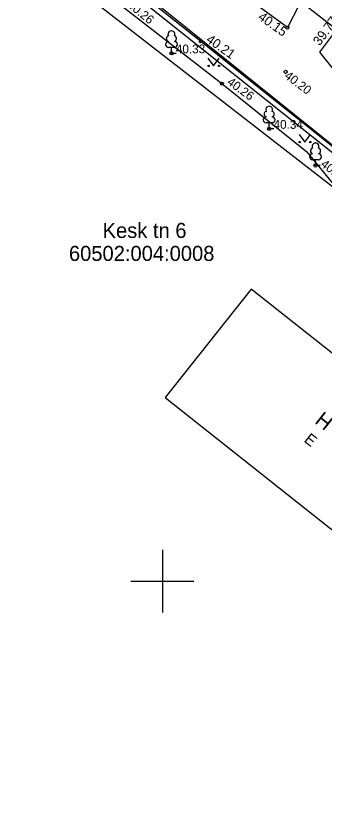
# Model space of a CAD drawing. Extents: x 641898 to 642452, y 6471715 to 6472255.
# Drawn here: x 642288.3 to 642312.9, y 6471781.7 to 6471845.1 of the extents above; entities that cross this region are included whole.
import ezdxf

# ---------------------------------------------------------------- set-up
doc = ezdxf.new("R2010")
doc.units = 0
for name, color, linetype in [('HALJASTUS', 7, 'Continuous'), ('HOONE', 7, 'Continuous'), ('KORGUS-EH2000', 7, 'Continuous'), ('KTRASS', 7, 'Continuous'), ('PIIR', 7, 'Continuous'), ('PUU', 7, 'Continuous'), ('TEE', 7, 'Continuous'), ('VORK', 7, 'Continuous'), ('VTRASS', 7, 'Continuous')]:
    doc.layers.add(name, color=color, linetype=linetype)

msp = doc.modelspace()

# ---------------------------------------------------------------- linework, layer by layer
at = {"layer": 'HALJASTUS'}
for p, q in [((642303.623, 6471841.712), (642304.087, 6471841.105)), ((642304.087, 6471841.105), (642304.532, 6471841.712)), ((642310.9, 6471835.642), (642311.363, 6471835.035)), ((642311.363, 6471835.035), (642311.809, 6471835.642))]:
    msp.add_line(p, q, dxfattribs=at)
msp.add_lwpolyline([(642288.49, 6471852.272), (642296.805, 6471845.864), (642304.75, 6471839.692), (642311.522, 6471834.256), (642313.79, 6471831.483)], dxfattribs=at)
for centre in [(642303.686, 6471841.105), (642304.514, 6471841.105), (642310.962, 6471835.035), (642311.791, 6471835.035)]:
    msp.add_circle(centre, 0.055, dxfattribs=at)
at = {"layer": 'HOONE'}
msp.add_lwpolyline([(642314.435, 6471817.467), (642307.082, 6471823.294), (642300.234, 6471814.661), (642317.624, 6471800.863), (642324.325, 6471809.63), (642317.037, 6471815.406), (642317.205, 6471815.618), (642314.604, 6471817.68), (642314.435, 6471817.467)], dxfattribs=at)
at = {"layer": 'KORGUS-EH2000'}
for centre in [(642309.969, 6471844.159), (642303.076, 6471843.066), (642300.726, 6471842.109), (642309.833, 6471840.631), (642304.75, 6471839.692), (642308.517, 6471836.089), (642312.216, 6471833.153)]:
    msp.add_circle(centre, 0.125, dxfattribs=at)
at = {"layer": 'KTRASS'}
msp.add_lwpolyline([(642324.897, 6471825.656), (642294.83, 6471849.849)], dxfattribs=at)
at = {"layer": 'PIIR'}
for p, q in [((642294.31, 6471859.27), (642377.02, 6471794.87)), ((642344.1, 6471807.76), (642288.16, 6471851.19))]:
    msp.add_line(p, q, dxfattribs=at)
at = {"layer": 'PUU'}
for p, q in [((642300.966, 6471842.584), (642300.486, 6471842.584)), ((642300.726, 6471842.109), (642300.726, 6471842.584)), ((642301.106, 6471842.109), (642300.726, 6471842.109)), ((642308.757, 6471836.564), (642308.277, 6471836.564)), ((642308.517, 6471836.089), (642308.517, 6471836.564)), ((642308.897, 6471836.089), (642308.517, 6471836.089)), ((642312.456, 6471833.628), (642311.976, 6471833.628)), ((642312.216, 6471833.153), (642312.216, 6471833.628)), ((642312.596, 6471833.153), (642312.216, 6471833.153))]:
    msp.add_line(p, q, dxfattribs=at)
for centre, radius, start, end in [((642300.726, 6471843.629), 0.277, 332.5799, 207.4201), ((642300.556, 6471843.282), 0.233, 109.02174, 253.14154), ((642300.896, 6471843.282), 0.233, 286.85082, 70.98591), ((642300.489, 6471842.821), 0.238, 90.0016, 269.3953), ((642300.963, 6471842.821), 0.238, 270.6047, 89.9984), ((642308.347, 6471837.262), 0.233, 109.02174, 253.14154), ((642308.517, 6471837.609), 0.277, 332.5799, 207.4201), ((642308.687, 6471837.262), 0.233, 286.85082, 70.98591), ((642308.28, 6471836.801), 0.238, 90.0016, 269.3953), ((642308.754, 6471836.801), 0.238, 270.6047, 89.9984), ((642312.216, 6471834.673), 0.277, 332.5799, 207.4201), ((642312.046, 6471834.326), 0.233, 109.02174, 253.14154), ((642312.386, 6471834.326), 0.233, 286.85082, 70.98591), ((642311.979, 6471833.865), 0.238, 90.0016, 269.3953), ((642312.453, 6471833.865), 0.238, 270.6047, 89.9984)]:
    msp.add_arc(centre, radius, start, end, dxfattribs=at)
at = {"layer": 'TEE'}
for points in [[(642366.559, 6471781.691), (642366.75, 6471785.551), (642365.695, 6471788.509), (642364.88, 6471791.554), (642359.32, 6471797.565), (642349.55, 6471805.814), (642345.029, 6471809.364), (642338.375, 6471814.612), (642330.338, 6471821.174), (642323.486, 6471826.682), (642313.328, 6471834.865), (642303.076, 6471843.066), (642293.352, 6471850.788), (642283.707, 6471858.589), (642276.578, 6471864.269), (642271.231, 6471868.612), (642264.701, 6471873.908), (642253.944, 6471882.162), (642243.566, 6471890.342)], [(642311.301, 6471846.781), (642309.969, 6471844.159), (642300.567, 6471851.05)], [(642383.211, 6471751.926), (642385.791, 6471761.757), (642386.251, 6471768.397), (642385.085, 6471777.246), (642381.999, 6471784.94), (642376.754, 6471790.765), (642370.195, 6471795.981), (642371.442, 6471797.485), (642368.827, 6471798.665), (642362.827, 6471801.747), (642353.417, 6471808.678), (642343.817, 6471816.473), (642335.394, 6471823.345), (642333.841, 6471824.933), (642323.652, 6471832.89), (642313.851, 6471840.582), (642312.566, 6471842.194), (642313.903, 6471844.023), (642314.481, 6471844.192), (642315.921, 6471842.975), (642316.454, 6471843.473), (642314.647, 6471845.18)]]:
    msp.add_lwpolyline(points, dxfattribs=at)
at = {"layer": 'VORK'}
for p, q in [((642300, 6471802.5), (642300, 6471797.5)), ((642297.5, 6471800), (642302.5, 6471800))]:
    msp.add_line(p, q, dxfattribs=at)
at = {"layer": 'VTRASS'}
msp.add_lwpolyline([(642383.722, 6471805.593), (642379.745, 6471805.698), (642375.961, 6471804.651), (642372.001, 6471801.12), (642371.83, 6471800.837), (642365.292, 6471792.802), (642334.532, 6471817.276), (642325.31, 6471824.815), (642293.796, 6471849.944), (642275.212, 6471864.371), (642256.629, 6471878.798), (642256.057, 6471879.253), (642241.436, 6471890.95)], dxfattribs=at)

# ---------------------------------------------------------------- texts
at = {"layer": 'HOONE'}
for s, height, p in [('H', 1.2, (642312.082, 6471812.673)), ('E', 0.9, (642311.231, 6471811.181))]:
    msp.add_text(s, height=height, rotation=321.57187, dxfattribs=at).set_placement(p)
at = {"layer": 'KORGUS-EH2000'}
for s, height, rotation, p in [('40.26', 0.7, 320.88712, (642297.155, 6471845.864)), ('40.15', 0.75, 324.73925, (642307.569, 6471844.864)), ('39.77', 0.75, 53.21273, (642312.546, 6471842.67)), ('40.21', 0.75, 324.96374, (642303.426, 6471843.066)), ('40.26', 0.7, 323.67907, (642305.1, 6471839.692)), ('40.20', 0.7, 322.74858, (642309.68, 6471840.194)), ('40.24', 0.7, 322.38295, (642312.566, 6471833.153))]:
    msp.add_text(s, height=height, rotation=rotation, dxfattribs=at).set_placement(p)
for s, p in [('40.33', (642301.076, 6471842.109)), ('40.34', (642308.867, 6471836.089))]:
    msp.add_text(s, height=0.7, dxfattribs=at).set_placement(p)
at = {"layer": 'PIIR'}
for s, p in [('Kesk tn 6', (642295.238, 6471827.384)), ('60502:004:0008', (642292.552, 6471825.552))]:
    msp.add_text(s, height=1.2, dxfattribs=at).set_placement(p)

doc.saveas('drawing.dxf')
